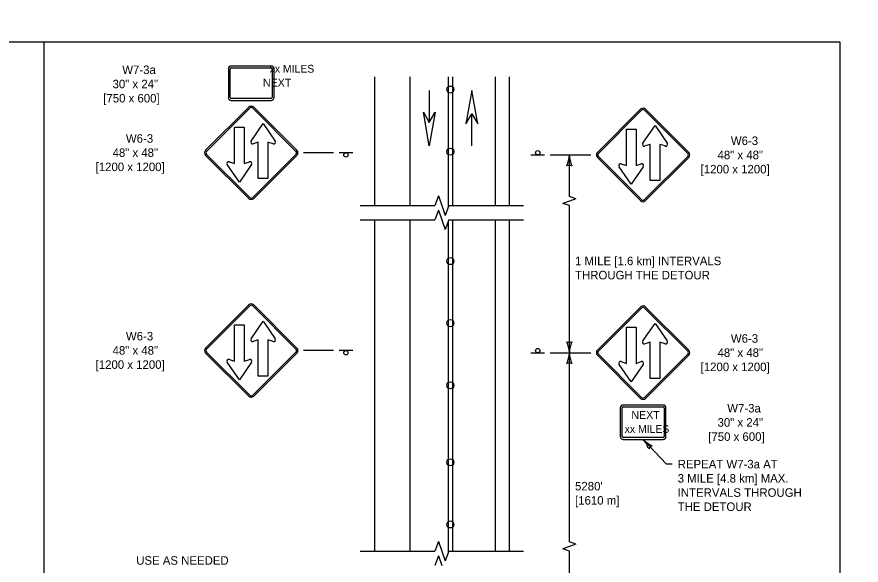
# Model space of a CAD drawing. Extents: x 49991.4 to 50021, y 49987.6 to 50011.4.
# Drawn here: x 50010.96 to 50016.9, y 49995.31 to 49999.18 of the extents above; entities that cross this region are included whole.
import ezdxf

# ---------------------------------------------------------------- set-up
doc = ezdxf.new("R2010")
doc.units = 0
for name, color, linetype in [('Level 1', 7, 'Continuous'), ('Level 2', 7, 'Continuous'), ('Level 3', 7, 'Continuous'), ('Level 6', 7, 'Continuous')]:
    doc.layers.add(name, color=color, linetype=linetype)

msp = doc.modelspace()

# ---------------------------------------------------------------- linework, layer by layer
at = {"layer": 'Level 1'}
for p, q in [((50016.9001, 49999.1756), (50016.9001, 49999.1756)), ((50012.7469, 49998.8292), (50012.4646, 49998.8292)), ((50012.4445, 49998.809), (50012.4445, 49998.6074)), ((50012.4579, 49998.6074), (50012.4579, 49998.809)), ((50012.4646, 49998.8157), (50012.7469, 49998.8157)), ((50012.7536, 49998.809), (50012.7536, 49998.6074)), ((50012.767, 49998.6074), (50012.767, 49998.809)), ((50013.4728, 49998.7525), (50013.4728, 49997.846)), ((50013.7228, 49998.7525), (50013.7228, 49997.846)), ((50013.9928, 49998.7525), (50013.9928, 49997.8358)), ((50014.0228, 49998.7525), (50014.0228, 49997.846)), ((50014.3228, 49998.7525), (50014.3228, 49997.846)), ((50014.4228, 49998.7525), (50014.4228, 49997.846)), ((50013.8595, 49998.6578), (50013.8595, 49998.432)), ((50013.8597, 49998.6578), (50013.8597, 49998.432)), ((50012.7469, 49998.6007), (50012.4646, 49998.6007)), ((50012.4646, 49998.5873), (50012.7469, 49998.5873)), ((50012.284, 49998.2358), (50012.5882, 49998.5398)), ((50012.2912, 49998.2286), (50012.5952, 49998.5328)), ((50012.6164, 49998.5328), (50012.9204, 49998.2286)), ((50012.6236, 49998.5398), (50012.9276, 49998.2358)), ((50015.0433, 49998.2208), (50015.3473, 49998.5248)), ((50015.3827, 49998.5248), (50015.6869, 49998.2208)), ((50014.1594, 49998.2678), (50014.1594, 49998.4936)), ((50014.1596, 49998.2678), (50014.1596, 49998.4936)), ((50015.0505, 49998.2138), (50015.3545, 49998.5178)), ((50015.3757, 49998.5178), (50015.6797, 49998.2138)), ((50012.6044, 49998.3006), (50012.6896, 49998.4244)), ((50012.6896, 49998.4244), (50012.7748, 49998.3006)), ((50015.3637, 49998.2858), (50015.4489, 49998.4094)), ((50015.4489, 49998.4094), (50015.5339, 49998.2858)), ((50012.488, 49998.3988), (50012.556, 49998.3988)), ((50012.488, 49998.1434), (50012.488, 49998.3988)), ((50012.556, 49998.3988), (50012.556, 49998.1434)), ((50015.2473, 49998.1282), (50015.2473, 49998.3838)), ((50015.2473, 49998.3838), (50015.3153, 49998.3838)), ((50015.3153, 49998.3838), (50015.3153, 49998.1282)), ((50012.6556, 49998.293), (50012.6192, 49998.281)), ((50012.6556, 49998.0374), (50012.6556, 49998.293)), ((50012.76, 49998.281), (50012.7236, 49998.293)), ((50012.7236, 49998.293), (50012.7236, 49998.0374)), ((50015.4149, 49998.2778), (50015.3785, 49998.2662)), ((50015.4149, 49998.0224), (50015.4149, 49998.2778)), ((50015.5193, 49998.2662), (50015.4829, 49998.2778)), ((50015.4829, 49998.2778), (50015.4829, 49998.0224)), ((50012.5882, 49997.8964), (50012.284, 49998.2004)), ((50012.5952, 49997.9034), (50012.2912, 49998.2074)), ((50012.9204, 49998.2074), (50012.6164, 49997.9034)), ((50012.9276, 49998.2004), (50012.6236, 49997.8964)), ((50013.3208, 49998.2182), (50013.2248, 49998.2182)), ((50014.5748, 49998.2031), (50014.6708, 49998.2031)), ((50015.3473, 49997.8814), (50015.0433, 49998.1854)), ((50015.3545, 49997.8884), (50015.0505, 49998.1926)), ((50015.6797, 49998.1926), (50015.3757, 49997.8884)), ((50015.6869, 49998.1854), (50015.3827, 49997.8814)), ((50012.522, 49998.0118), (50012.437, 49998.1354)), ((50012.4516, 49998.155), (50012.488, 49998.1434)), ((50012.6072, 49998.1354), (50012.522, 49998.0118)), ((50012.556, 49998.1434), (50012.5924, 49998.155)), ((50015.2813, 49997.9968), (50015.1961, 49998.1206)), ((50015.2109, 49998.1402), (50015.2473, 49998.1282)), ((50015.3665, 49998.1206), (50015.2813, 49997.9968)), ((50015.3153, 49998.1282), (50015.3517, 49998.1402)), ((50012.7236, 49998.0374), (50012.6556, 49998.0374)), ((50015.4829, 49998.0224), (50015.4149, 49998.0224)), ((50013.4728, 49997.746), (50013.4728, 49995.4125)), ((50013.7228, 49997.746), (50013.7228, 49995.4125)), ((50013.9928, 49997.7358), (50013.9928, 49995.4023)), ((50014.0228, 49997.746), (50014.0228, 49995.4125)), ((50014.3228, 49997.746), (50014.3228, 49995.4125)), ((50014.4228, 49997.746), (50014.4228, 49995.4125)), ((50012.284, 49996.8433), (50012.5882, 49997.1473)), ((50012.2912, 49996.8361), (50012.5952, 49997.1403)), ((50012.6164, 49997.1403), (50012.9204, 49996.8361)), ((50012.6236, 49997.1473), (50012.9276, 49996.8433)), ((50015.0433, 49996.8281), (50015.3473, 49997.1321)), ((50015.0505, 49996.8211), (50015.3545, 49997.1251)), ((50015.3757, 49997.1251), (50015.6797, 49996.8211)), ((50015.3827, 49997.1321), (50015.6869, 49996.8281)), ((50012.488, 49997.0063), (50012.556, 49997.0063)), ((50012.488, 49996.7509), (50012.488, 49997.0063)), ((50012.556, 49997.0063), (50012.556, 49996.7509)), ((50012.6044, 49996.9081), (50012.6896, 49997.0319)), ((50012.6896, 49997.0319), (50012.7748, 49996.9081)), ((50015.2473, 49996.7355), (50015.2473, 49996.9911)), ((50015.2473, 49996.9911), (50015.3153, 49996.9911)), ((50015.3153, 49996.9911), (50015.3153, 49996.7355)), ((50015.3637, 49996.8931), (50015.4489, 49997.0167)), ((50015.4489, 49997.0167), (50015.5339, 49996.8931)), ((50012.6556, 49996.9005), (50012.6192, 49996.8885)), ((50012.6556, 49996.6449), (50012.6556, 49996.9005)), ((50012.76, 49996.8885), (50012.7236, 49996.9005)), ((50012.7236, 49996.9005), (50012.7236, 49996.6449)), ((50015.4149, 49996.8851), (50015.3785, 49996.8735)), ((50015.4149, 49996.6297), (50015.4149, 49996.8851)), ((50015.5193, 49996.8735), (50015.4829, 49996.8851)), ((50015.4829, 49996.8851), (50015.4829, 49996.6297)), ((50012.5882, 49996.5039), (50012.284, 49996.8079)), ((50012.5952, 49996.5109), (50012.2912, 49996.8149)), ((50012.9204, 49996.8149), (50012.6164, 49996.5109)), ((50012.9276, 49996.8079), (50012.6236, 49996.5039)), ((50013.3208, 49996.8257), (50013.2248, 49996.8257)), ((50014.5748, 49996.8105), (50014.6708, 49996.8105)), ((50015.3545, 49996.4957), (50015.0505, 49996.7999)), ((50015.6797, 49996.7999), (50015.3757, 49996.4957)), ((50012.522, 49996.6193), (50012.437, 49996.7429)), ((50012.4516, 49996.7625), (50012.488, 49996.7509)), ((50012.6072, 49996.7429), (50012.522, 49996.6193)), ((50012.556, 49996.7509), (50012.5924, 49996.7625)), ((50015.3473, 49996.4887), (50015.0433, 49996.7927)), ((50015.2109, 49996.7475), (50015.2473, 49996.7355)), ((50015.3153, 49996.7355), (50015.3517, 49996.7475)), ((50015.6869, 49996.7927), (50015.3827, 49996.4887)), ((50015.2813, 49996.6041), (50015.1961, 49996.7279)), ((50015.3665, 49996.7279), (50015.2813, 49996.6041)), ((50012.7236, 49996.6449), (50012.6556, 49996.6449)), ((50015.4829, 49996.6297), (50015.4149, 49996.6297)), ((50015.506, 49996.4414), (50015.2237, 49996.4414)), ((50015.2036, 49996.4213), (50015.2036, 49996.2197)), ((50015.217, 49996.2197), (50015.217, 49996.4213)), ((50015.2237, 49996.428), (50015.506, 49996.428)), ((50015.5127, 49996.4213), (50015.5127, 49996.2197)), ((50015.5261, 49996.2197), (50015.5261, 49996.4213)), ((50015.506, 49996.213), (50015.2237, 49996.213)), ((50015.2237, 49996.1995), (50015.506, 49996.1995))]:
    msp.add_line(p, q, dxfattribs=at)
for points in [[(49999.3835, 49998.9992), (50016.7501, 49998.9992), (50016.7501, 49987.7988), (49999.3835, 49987.7988)], [(50014.2014, 49998.4214), (50014.1596, 49998.6578), (50014.1178, 49998.4214), (50014.1596, 49998.4934)], [(50013.9015, 49998.5042), (50013.8597, 49998.2678), (50013.8179, 49998.5042), (50013.8597, 49998.4322)]]:
    msp.add_lwpolyline(points, close=True, dxfattribs=at)
for centre, radius in [((50014.0079, 49998.6635), 0.025), ((50014.0079, 49998.226), 0.025), ((50014.6229, 49998.2182), 0.0152), ((50013.2727, 49998.2031), 0.0152), ((50014.0079, 49997.4558), 0.025), ((50014.0079, 49997.0183), 0.025), ((50013.2727, 49996.8105), 0.0152), ((50014.6229, 49996.8257), 0.0152), ((50014.0079, 49996.5808), 0.025), ((50014.0079, 49996.0385), 0.025), ((50014.0079, 49995.601), 0.025)]:
    msp.add_circle(centre, radius, dxfattribs=at)
for centre, radius, start, end in [((50012.4646, 49998.809), 0.0202, 90, 180), ((50012.7469, 49998.809), 0.0202, 360, 90), ((50012.4646, 49998.809), 0.00672, 90, 180), ((50012.7469, 49998.809), 0.00672, 360, 90), ((50012.4646, 49998.6074), 0.0202, 180, 270), ((50012.4646, 49998.6074), 0.00672, 180, 270), ((50012.7469, 49998.6074), 0.00672, 270, 360), ((50012.7469, 49998.6074), 0.0202, 270, 360), ((50012.6057, 49998.5223), 0.025, 45.00043, 135), ((50012.6057, 49998.5223), 0.015, 45.00043, 135), ((50015.3649, 49998.5072), 0.025, 45, 135), ((50015.3649, 49998.5072), 0.015, 45, 135), ((50012.6151, 49998.2935), 0.0129, 145.58495, 216.71634), ((50012.6151, 49998.2935), 0.0129, 216.71939, 287.95818), ((50012.7639, 49998.2935), 0.0129, 252.04182, 323.27756), ((50012.7639, 49998.2935), 0.0129, 323.28061, 34.51941), ((50015.3742, 49998.2784), 0.0129, 145.58495, 216.71634), ((50015.5231, 49998.2784), 0.0129, 323.28061, 34.51941), ((50012.3017, 49998.2182), 0.025, 135, 225), ((50012.3017, 49998.2182), 0.015, 135, 225), ((50012.9098, 49998.2182), 0.015, 314.99976, 45), ((50012.9098, 49998.2182), 0.025, 314.99976, 45), ((50015.3742, 49998.2784), 0.0129, 216.71939, 287.95818), ((50015.5231, 49998.2784), 0.0129, 252.04182, 323.27756), ((50015.0608, 49998.2031), 0.025, 134.99976, 225), ((50015.0608, 49998.2031), 0.015, 134.99976, 225), ((50015.6689, 49998.2031), 0.015, 315, 45), ((50015.6689, 49998.2031), 0.025, 315, 45), ((50012.4475, 49998.1429), 0.0129, 143.28061, 214.51941), ((50012.4475, 49998.1429), 0.0129, 72.04182, 143.27756), ((50012.5964, 49998.1429), 0.0129, 36.71939, 107.95818), ((50012.5964, 49998.1429), 0.0129, 325.58495, 36.71634), ((50015.2067, 49998.1278), 0.0129, 143.28061, 214.51941), ((50015.2067, 49998.1278), 0.0129, 72.04182, 143.27756), ((50015.3555, 49998.1278), 0.0129, 36.71939, 107.95818), ((50015.3555, 49998.1278), 0.0129, 325.58495, 36.71634), ((50012.6057, 49997.9141), 0.025, 225, 315), ((50012.6057, 49997.9141), 0.015, 225, 315), ((50015.3649, 49997.899), 0.025, 225.00043, 315), ((50015.3649, 49997.899), 0.015, 225.00043, 315), ((50012.6057, 49997.1298), 0.025, 45.00043, 135), ((50012.6057, 49997.1298), 0.015, 45.00043, 135), ((50015.3649, 49997.1146), 0.025, 45, 135), ((50015.3649, 49997.1146), 0.015, 45, 135), ((50012.6151, 49996.901), 0.0129, 145.58495, 216.71634), ((50012.6151, 49996.901), 0.0129, 216.71939, 287.95818), ((50012.7639, 49996.901), 0.0129, 252.04182, 323.27756), ((50012.7639, 49996.901), 0.0129, 323.28061, 34.51941), ((50015.3742, 49996.8858), 0.0129, 145.58495, 216.71634), ((50015.3742, 49996.8858), 0.0129, 216.71939, 287.95818), ((50015.5231, 49996.8858), 0.0129, 252.04182, 323.27756), ((50015.5231, 49996.8858), 0.0129, 323.28061, 34.51941), ((50012.3017, 49996.8257), 0.025, 135, 225), ((50012.3017, 49996.8257), 0.015, 135, 225), ((50012.9098, 49996.8257), 0.015, 314.99976, 45), ((50012.9098, 49996.8257), 0.025, 314.99976, 45), ((50015.0608, 49996.8105), 0.025, 134.99976, 225), ((50015.0608, 49996.8105), 0.015, 134.99976, 225), ((50015.6689, 49996.8105), 0.015, 315, 45), ((50015.6689, 49996.8105), 0.025, 315, 45), ((50012.4475, 49996.7504), 0.0129, 143.28061, 214.51941), ((50012.4475, 49996.7504), 0.0129, 72.04182, 143.27756), ((50012.5964, 49996.7504), 0.0129, 36.71939, 107.95818), ((50012.5964, 49996.7504), 0.0129, 325.58495, 36.71634), ((50015.2067, 49996.7352), 0.0129, 143.28061, 214.51941), ((50015.2067, 49996.7352), 0.0129, 72.04182, 143.27756), ((50015.3555, 49996.7352), 0.0129, 36.71939, 107.95818), ((50015.3555, 49996.7352), 0.0129, 325.58495, 36.71634), ((50012.6057, 49996.5216), 0.025, 225, 315), ((50012.6057, 49996.5216), 0.015, 225, 315), ((50015.2237, 49996.4213), 0.0202, 90, 180), ((50015.3649, 49996.5064), 0.025, 225.00043, 315), ((50015.3649, 49996.5064), 0.015, 225.00043, 315), ((50015.506, 49996.4213), 0.0202, 0, 90), ((50015.2237, 49996.4213), 0.00672, 90, 180), ((50015.506, 49996.4213), 0.00672, 0, 90), ((50015.2237, 49996.2197), 0.0202, 180, 270), ((50015.2237, 49996.2197), 0.00672, 180, 270), ((50015.506, 49996.2197), 0.00672, 270, 360), ((50015.506, 49996.2197), 0.0202, 270, 360)]:
    msp.add_arc(centre, radius, start, end, dxfattribs=at)
at = {"layer": 'Level 3'}
for p, q in [((50011.1455, 49998.9992), (50011.1455, 49987.7988)), ((50013.1848, 49998.2182), (50012.9748, 49998.2182)), ((50014.7108, 49998.2031), (50014.9958, 49998.2031)), ((50014.8458, 49997.9108), (50014.8458, 49998.2031)), ((50014.8458, 49997.8784), (50014.8001, 49997.8622)), ((50014.8915, 49997.8946), (50014.8458, 49997.9108)), ((50014.8915, 49997.8946), (50014.8458, 49997.8784)), ((50014.8458, 49997.846), (50014.8001, 49997.8622)), ((50014.8458, 49996.8105), (50014.8458, 49997.846)), ((50013.1848, 49996.8257), (50012.9748, 49996.8257)), ((50014.7108, 49996.8105), (50014.9958, 49996.8105)), ((50014.8458, 49995.4773), (50014.8458, 49996.8105)), ((50015.5286, 49996.0255), (50015.3649, 49996.1995)), ((50015.5686, 49996.0255), (50015.5286, 49996.0255)), ((50014.8458, 49995.4449), (50014.8001, 49995.4287)), ((50014.8458, 49995.4125), (50014.8001, 49995.4287)), ((50014.8915, 49995.4611), (50014.8458, 49995.4773)), ((50014.8915, 49995.4611), (50014.8458, 49995.4449)), ((50014.8458, 49994.869), (50014.8458, 49995.4125))]:
    msp.add_line(p, q, dxfattribs=at)
for centre, radius, start, end in [((50014.6237, 49998.2123), 0.2223, 337.45601, 357.63952), ((50015.0785, 49998.2146), 0.233, 182.82731, 202.07716), ((50014.8458, 49998.0749), 0.0548, 72.13882, 107.86118), ((50014.8458, 49996.9387), 0.0548, 252.13882, 287.86118), ((50014.6131, 49996.799), 0.233, 2.82731, 22.07716), ((50015.0679, 49996.8013), 0.2223, 157.45601, 177.63952), ((50014.6237, 49996.8197), 0.2223, 337.45601, 357.63952), ((50015.0785, 49996.822), 0.233, 182.82731, 202.07716), ((50014.8458, 49996.6823), 0.0548, 72.13882, 107.86118), ((50015.1968, 49996.054), 0.2223, 20.71512, 40.89862), ((50015.5265, 49996.3674), 0.233, 226.08642, 245.33627), ((50015.4527, 49996.1061), 0.0548, 115.39792, 151.12028)]:
    msp.add_arc(centre, radius, start, end, dxfattribs=at)
at = {"layer": 'Level 6'}
for p, q in [((50013.9236, 49997.9144), (50013.8992, 49997.846)), ((50013.9236, 49997.9144), (50013.9478, 49997.846)), ((50013.3728, 49997.846), (50013.8992, 49997.846)), ((50013.9236, 49997.8144), (50013.8992, 49997.746)), ((50013.9236, 49997.8144), (50013.9478, 49997.746)), ((50013.9478, 49997.846), (50013.972, 49997.7772)), ((50013.9964, 49997.846), (50013.972, 49997.7772)), ((50013.9964, 49997.846), (50014.5228, 49997.846)), ((50013.3728, 49997.746), (50013.8992, 49997.746)), ((50013.9478, 49997.746), (50013.972, 49997.6772)), ((50013.9964, 49997.746), (50013.972, 49997.6772)), ((50013.9964, 49997.746), (50014.5228, 49997.746)), ((50013.9236, 49995.4809), (50013.8992, 49995.4125)), ((50013.9236, 49995.4809), (50013.9478, 49995.4125)), ((50013.3728, 49995.4125), (50013.8992, 49995.4125)), ((50013.9236, 49995.3809), (50013.8992, 49995.3125)), ((50013.9236, 49995.3809), (50013.9478, 49995.3125)), ((50013.9478, 49995.4125), (50013.972, 49995.3437)), ((50013.9964, 49995.4125), (50013.972, 49995.3437)), ((50013.9964, 49995.4125), (50014.5228, 49995.4125))]:
    msp.add_line(p, q, dxfattribs=at)

# ---------------------------------------------------------------- texts
at = {"layer": 'Level 1'}
for s, height, p in [('xx MILES', 0.05493, (50012.7352, 49998.7828)), ('NEXT', 0.05599, (50012.6882, 49998.6846))]:
    msp.add_text(s, height=height, rotation=360, dxfattribs=at).set_placement(p)
for s, height, p in [('NEXT', 0.05599, (50015.2824, 49996.3441)), ('xx MILES', 0.05493, (50015.2354, 49996.2459))]:
    msp.add_text(s, height=height, dxfattribs=at).set_placement(p)
at = {"layer": 'Level 2'}
for s, p in [('W7-3a', (50011.6977, 49998.7729)), ('30" x 24"', (50011.6293, 49998.6729)), ('[750 x 600]', (50011.5637, 49998.5729)), ('W6-3', (50011.7232, 49998.2892)), ('W6-3', (50015.9831, 49998.2731)), ('48" x 48"', (50011.6294, 49998.1892)), ('48" x 48"', (50015.8893, 49998.1731)), ('[1200 x 1200]', (50011.51, 49998.0892)), ('[1200 x 1200]', (50015.7699, 49998.0731)), ('1 MILE [1.6 km] INTERVALS ', (50014.8858, 49997.4268)), ('THROUGH THE DETOUR ', (50014.8858, 49997.3268)), ('W6-3', (50011.7232, 49996.8967)), ('W6-3', (50015.9831, 49996.8805)), ('48" x 48"', (50011.6294, 49996.7967)), ('48" x 48"', (50015.8893, 49996.7805)), ('[1200 x 1200]', (50011.51, 49996.6967)), ('[1200 x 1200]', (50015.7699, 49996.6805)), ('W7-3a', (50015.9577, 49996.3894)), ('30" x 24"', (50015.8893, 49996.2894)), ('[750 x 600]', (50015.8238, 49996.1894)), ('REPEAT W7-3a AT ', (50015.6086, 49995.9955)), ('3 MILE [4.8 km] MAX.', (50015.6086, 49995.8955)), ("5280' ", (50014.8858, 49995.8404)), ('INTERVALS THROUGH', (50015.6086, 49995.7955)), ('[1610 m]', (50014.8858, 49995.7404)), ('THE DETOUR', (50015.6086, 49995.6955)), ('USE AS NEEDED', (50011.7958, 49995.3171))]:
    msp.add_text(s, height=0.06, dxfattribs=at).set_placement(p)

doc.saveas('drawing.dxf')
